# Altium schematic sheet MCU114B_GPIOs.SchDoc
size 431 x 279 mm; Date: Not shown in title block; ApprovedBy: Not shown in title block; CheckedBy: Not shown in title block; Author: Not shown in title block; CompanyName: Not shown in title block; Engineer: Not shown in title block; Organization: Not shown in title block; Address1: Not shown in title block; Address2: Not shown in title block; Address3: Not shown in title block; Address4: Not shown in title block; DocumentNumber: 2; Revision: Use project parameter SCH_Rev; SheetNumber: 2; SheetTotal: 11; PageSetup: Record=PageOptions¦CenterHorizontal=True¦CenterVertical=True¦PrintScale=1.00¦XCorrection=1.00¦YCorrection=1.00¦PrintKind=0¦BorderSize=5000000¦LeftOffset=0¦BottomOffset=0¦Orientation=2¦PaperLength=1000¦PaperWidth=1000¦Scale=100¦PaperSource=15¦PrintQuality=600¦MediaType=1¦DitherType=10¦PaperKind=Letter¦PrintScaleMode=1
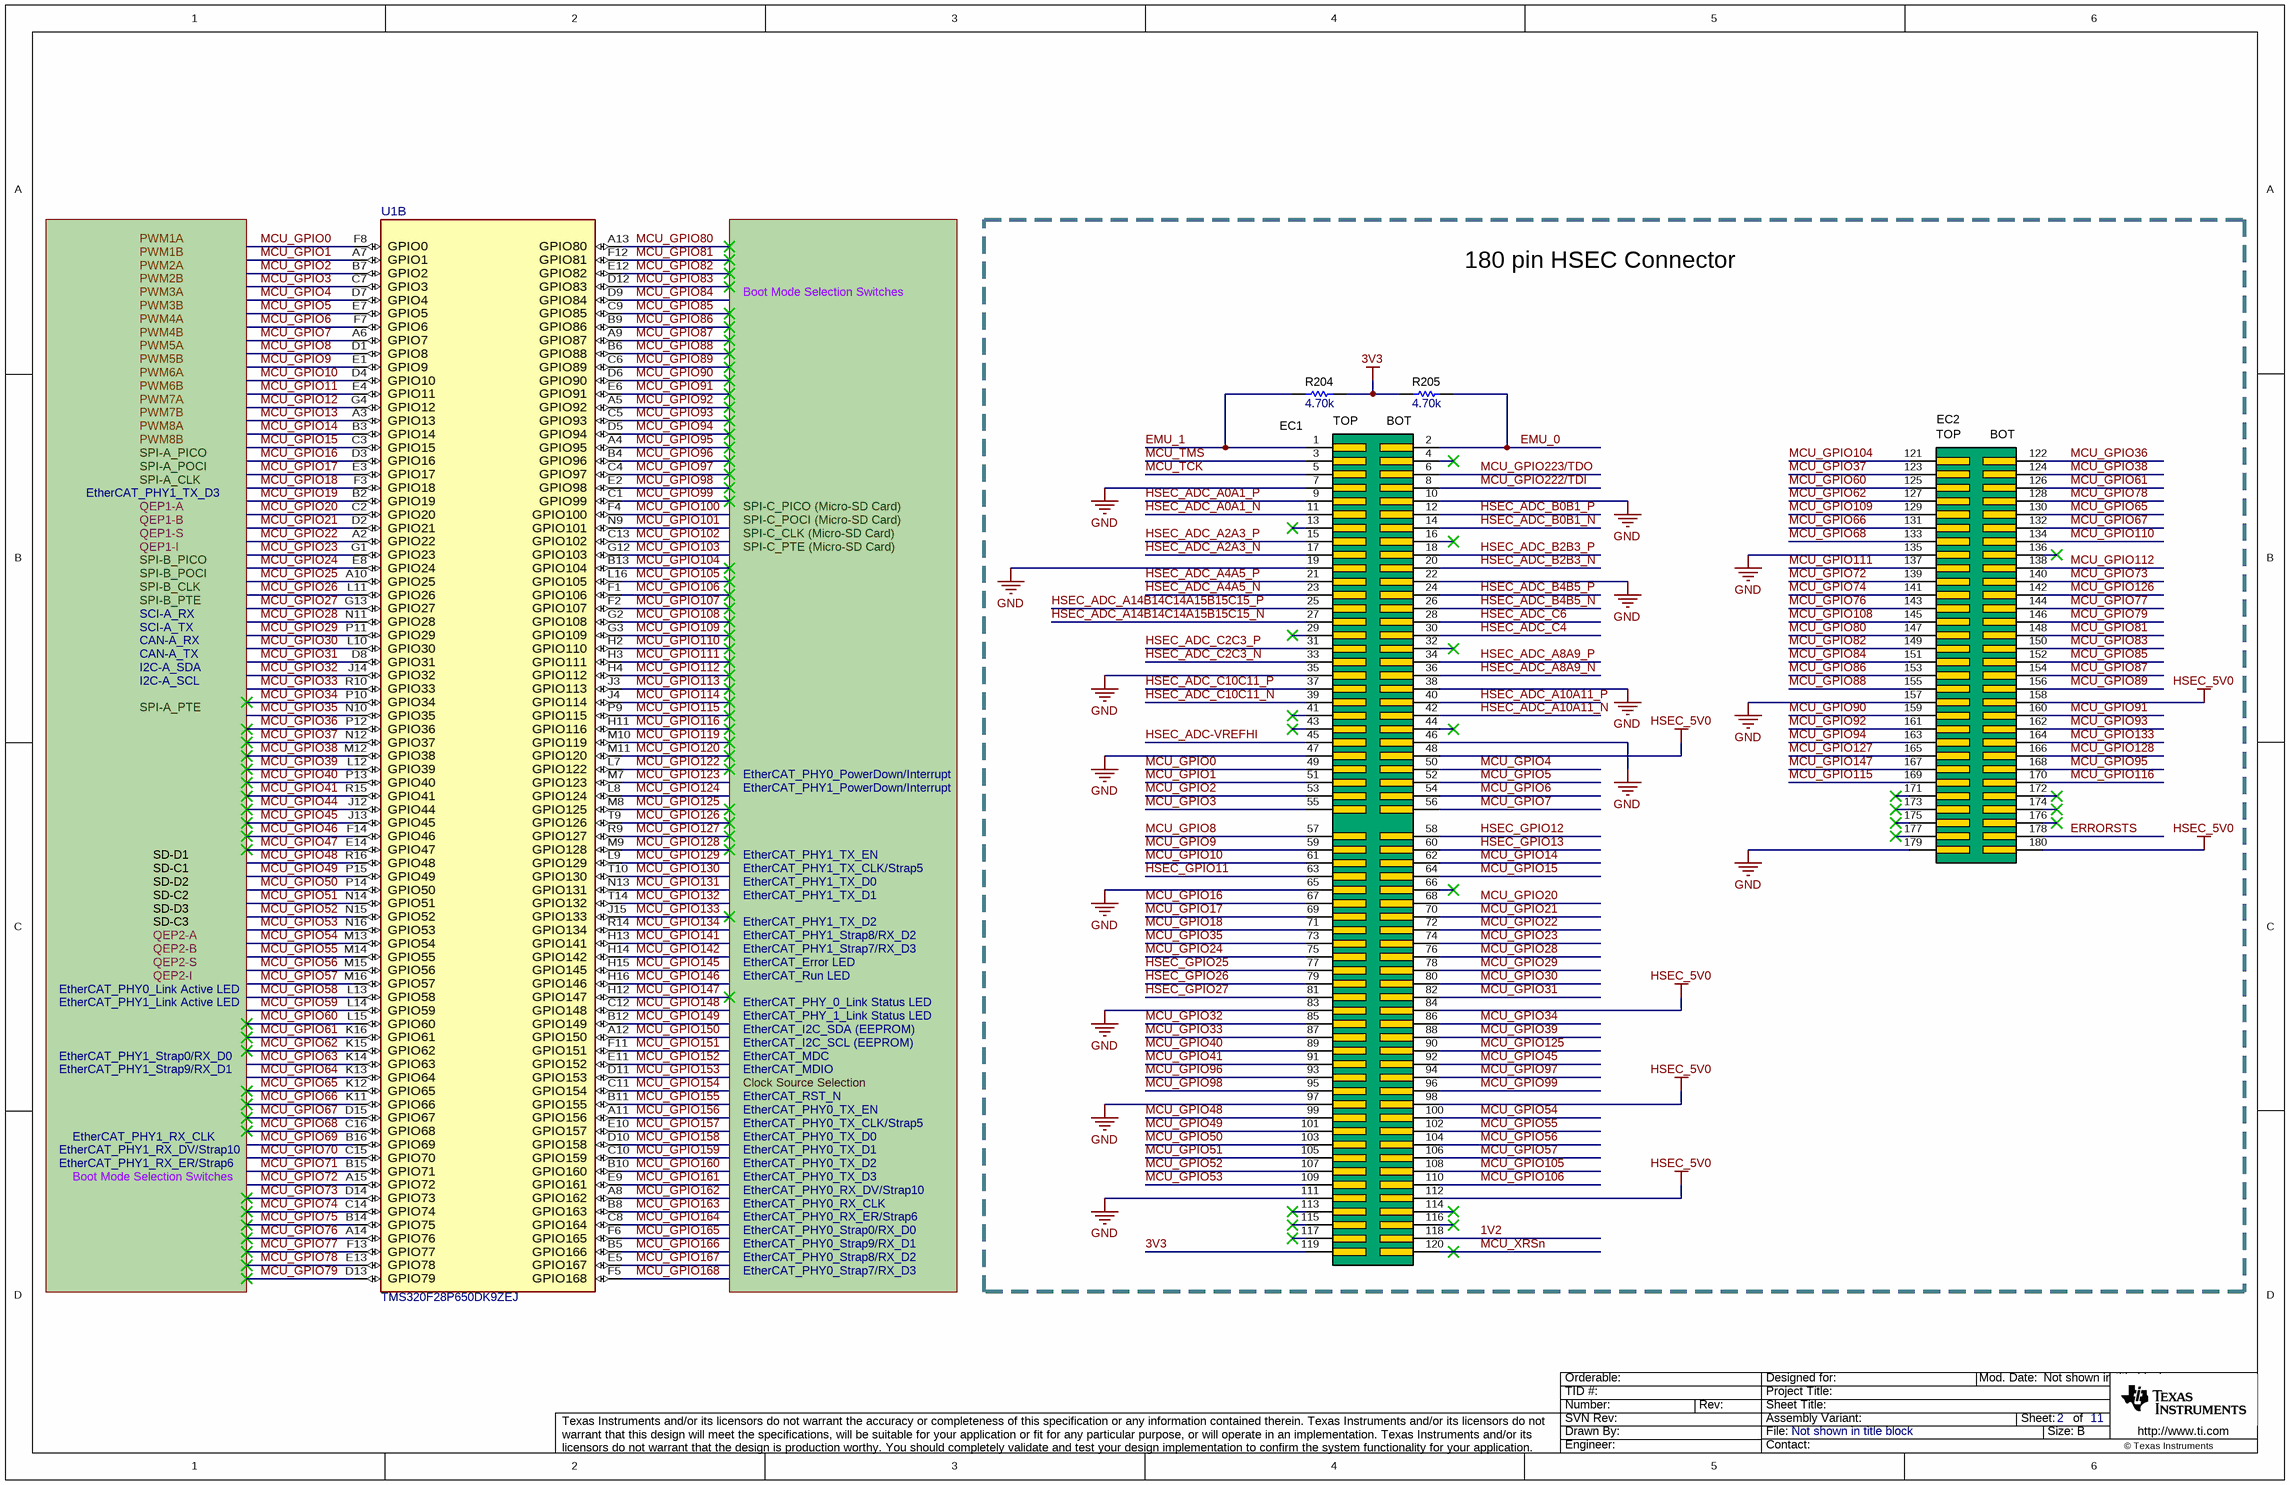
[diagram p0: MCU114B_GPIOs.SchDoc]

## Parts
EC1  controlCARD-120HSEC_Edge  [controlCARD-120HSEC_Edge]  (value not drawn)  (no BOM)
EC2  controlCARD-180HSEC-60pinAddon_Edge  [controlCARD-180HSEC-60pinAddon_Edge]  (value not drawn)  (no BOM)
R204  ValueDisplayed: 4.70k  [0402]  (hidden comment: CRG0402F4K7)
R205  ValueDisplayed: 4.70k  [0402]  (hidden comment: CRG0402F4K7)
U1  TMS320F28P650DK9ZEJ  [ZEJ0256A-MFG]  (part B of 4)

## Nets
3V3: EC1.119 R204.2 R205.1
GND: EC1.7 EC1.10 EC1.19 EC1.22 EC1.35 EC1.38 EC1.46 EC1.47 EC1.65 EC1.83 EC1.97 EC1.111 EC2.135 EC2.157 EC2.179
HSEC_5V0: EC1.48 EC1.84 EC1.98 EC1.112 EC2.158 EC2.180
1V2: EC1.118
EMU_0: EC1.2 R205.2
EMU_1: EC1.1 R204.1
ERRORSTS: EC2.178
HSEC_ADC-VREFHI: EC1.45
HSEC_ADC_A0A1_N: EC1.11
HSEC_ADC_A0A1_P: EC1.9
HSEC_ADC_A2A3_N: EC1.17
HSEC_ADC_A2A3_P: EC1.15
HSEC_ADC_A4A5_N: EC1.23
HSEC_ADC_A4A5_P: EC1.21
HSEC_ADC_A8A9_N: EC1.36
HSEC_ADC_A8A9_P: EC1.34
HSEC_ADC_A10A11_N: EC1.42
HSEC_ADC_A10A11_P: EC1.40
HSEC_ADC_A14B14C14A15B15C15_N: EC1.27
HSEC_ADC_A14B14C14A15B15C15_P: EC1.25
HSEC_ADC_B0B1_N: EC1.14
HSEC_ADC_B0B1_P: EC1.12
HSEC_ADC_B2B3_N: EC1.20
HSEC_ADC_B2B3_P: EC1.18
HSEC_ADC_B4B5_N: EC1.26
HSEC_ADC_B4B5_P: EC1.24
HSEC_ADC_C2C3_N: EC1.33
HSEC_ADC_C2C3_P: EC1.31
HSEC_ADC_C4: EC1.30
HSEC_ADC_C6: EC1.28
HSEC_ADC_C10C11_N: EC1.39
HSEC_ADC_C10C11_P: EC1.37
HSEC_GPIO11: EC1.63
HSEC_GPIO12: EC1.58
HSEC_GPIO13: EC1.60
HSEC_GPIO25: EC1.77
HSEC_GPIO26: EC1.79
HSEC_GPIO27: EC1.81
MCU_GPIO0: EC1.49 U1.F8(GPIO0)
MCU_GPIO1: EC1.51 U1.A7(GPIO1)
MCU_GPIO2: EC1.53 U1.B7(GPIO2)
MCU_GPIO3: EC1.55 U1.C7(GPIO3)
MCU_GPIO4: EC1.50 U1.D7(GPIO4)
MCU_GPIO5: EC1.52 U1.E7(GPIO5)
MCU_GPIO6: EC1.54 U1.F7(GPIO6)
MCU_GPIO7: EC1.56 U1.A6(GPIO7)
MCU_GPIO8: EC1.57 U1.D1(GPIO8)
MCU_GPIO9: EC1.59 U1.E1(GPIO9)
MCU_GPIO10: EC1.61 U1.D4(GPIO10)
MCU_GPIO11: U1.E4(GPIO11)
MCU_GPIO12: U1.G4(GPIO12)
MCU_GPIO13: U1.A3(GPIO13)
MCU_GPIO14: EC1.62 U1.B3(GPIO14)
MCU_GPIO15: EC1.64 U1.C3(GPIO15)
MCU_GPIO16: EC1.67 U1.D3(GPIO16)
MCU_GPIO17: EC1.69 U1.E3(GPIO17)
MCU_GPIO18: EC1.71 U1.F3(GPIO18)
MCU_GPIO19: U1.B2(GPIO19)
MCU_GPIO20: EC1.68 U1.C2(GPIO20)
MCU_GPIO21: EC1.70 U1.D2(GPIO21)
MCU_GPIO22: EC1.72 U1.A2(GPIO22)
MCU_GPIO23: EC1.74 U1.G1(GPIO23)
MCU_GPIO24: EC1.75 U1.E8(GPIO24)
MCU_GPIO25: U1.A10(GPIO25)
MCU_GPIO26: U1.L11(GPIO26)
MCU_GPIO27: U1.G13(GPIO27)
MCU_GPIO28: EC1.76 U1.N11(GPIO28)
MCU_GPIO29: EC1.78 U1.P11(GPIO29)
MCU_GPIO30: EC1.80 U1.L10(GPIO30)
MCU_GPIO31: EC1.82 U1.D8(GPIO31)
MCU_GPIO32: EC1.85 U1.J14(GPIO32)
MCU_GPIO33: EC1.87 U1.R10(GPIO33)
MCU_GPIO34: EC1.86 U1.P10(GPIO34)
MCU_GPIO35: EC1.73 U1.N10(GPIO35)
MCU_GPIO36: EC2.122 U1.P12(GPIO36)
MCU_GPIO37: EC2.123 U1.N12(GPIO37)
MCU_GPIO38: EC2.124 U1.M12(GPIO38)
MCU_GPIO39: EC1.88 U1.L12(GPIO39)
MCU_GPIO40: EC1.89 U1.P13(GPIO40)
MCU_GPIO41: EC1.91 U1.R15(GPIO41)
MCU_GPIO44: U1.J12(GPIO44)
MCU_GPIO45: EC1.92 U1.J13(GPIO45)
MCU_GPIO46: U1.F14(GPIO46)
MCU_GPIO47: U1.E14(GPIO47)
MCU_GPIO48: EC1.99 U1.R16(GPIO48)
MCU_GPIO49: EC1.101 U1.P15(GPIO49)
MCU_GPIO50: EC1.103 U1.P14(GPIO50)
MCU_GPIO51: EC1.105 U1.N14(GPIO51)
MCU_GPIO52: EC1.107 U1.N15(GPIO52)
MCU_GPIO53: EC1.109 U1.N16(GPIO53)
MCU_GPIO54: EC1.100 U1.M13(GPIO54)
MCU_GPIO55: EC1.102 U1.M14(GPIO55)
MCU_GPIO56: EC1.104 U1.M15(GPIO56)
MCU_GPIO57: EC1.106 U1.M16(GPIO57)
MCU_GPIO58: U1.L13(GPIO58)
MCU_GPIO59: U1.L14(GPIO59)
MCU_GPIO60: EC2.125 U1.L15(GPIO60)
MCU_GPIO61: EC2.126 U1.K16(GPIO61)
MCU_GPIO62: EC2.127 U1.K15(GPIO62)
MCU_GPIO63: U1.K14(GPIO63)
MCU_GPIO64: U1.K13(GPIO64)
MCU_GPIO65: EC2.130 U1.K12(GPIO65)
MCU_GPIO66: EC2.131 U1.K11(GPIO66)
MCU_GPIO67: EC2.132 U1.D15(GPIO67)
MCU_GPIO68: EC2.133 U1.C16(GPIO68)
MCU_GPIO69: U1.B16(GPIO69)
MCU_GPIO70: U1.C15(GPIO70)
MCU_GPIO71: U1.B15(GPIO71)
MCU_GPIO72: EC2.139 U1.A15(GPIO72)
MCU_GPIO73: EC2.140 U1.D14(GPIO73)
MCU_GPIO74: EC2.141 U1.C14(GPIO74)
MCU_GPIO75: U1.B14(GPIO75)
MCU_GPIO76: EC2.143 U1.A14(GPIO76)
MCU_GPIO77: EC2.144 U1.F13(GPIO77)
MCU_GPIO78: EC2.128 U1.E13(GPIO78)
MCU_GPIO79: EC2.146 U1.D13(GPIO79)
MCU_GPIO80: EC2.147 U1.A13(GPIO80)
MCU_GPIO81: EC2.148 U1.F12(GPIO81)
MCU_GPIO82: EC2.149 U1.E12(GPIO82)
MCU_GPIO83: EC2.150 U1.D12(GPIO83)
MCU_GPIO84: EC2.151 U1.D9(GPIO84)
MCU_GPIO85: EC2.152 U1.C9(GPIO85)
MCU_GPIO86: EC2.153 U1.B9(GPIO86)
MCU_GPIO87: EC2.154 U1.A9(GPIO87)
MCU_GPIO88: EC2.155 U1.B6(GPIO88)
MCU_GPIO89: EC2.156 U1.C6(GPIO89)
MCU_GPIO90: EC2.159 U1.D6(GPIO90)
MCU_GPIO91: EC2.160 U1.E6(GPIO91)
MCU_GPIO92: EC2.161 U1.A5(GPIO92)
MCU_GPIO93: EC2.162 U1.C5(GPIO93)
MCU_GPIO94: EC2.163 U1.D5(GPIO94)
MCU_GPIO95: EC2.168 U1.A4(GPIO95)
MCU_GPIO96: EC1.93 U1.B4(GPIO96)
MCU_GPIO97: EC1.94 U1.C4(GPIO97)
MCU_GPIO98: EC1.95 U1.E2(GPIO98)
MCU_GPIO99: EC1.96 U1.C1(GPIO99)
MCU_GPIO100: U1.F4(GPIO100)
MCU_GPIO101: U1.N9(GPIO101)
MCU_GPIO102: U1.C13(GPIO102)
MCU_GPIO103: U1.G12(GPIO103)
MCU_GPIO104: EC2.121 U1.B13(GPIO104)
MCU_GPIO105: EC1.108 U1.L16(GPIO105)
MCU_GPIO106: EC1.110 U1.F1(GPIO106)
MCU_GPIO107: U1.F2(GPIO107)
MCU_GPIO108: EC2.145 U1.G2(GPIO108)
MCU_GPIO109: EC2.129 U1.G3(GPIO109)
MCU_GPIO110: EC2.134 U1.H2(GPIO110)
MCU_GPIO111: EC2.137 U1.H3(GPIO111)
MCU_GPIO112: EC2.138 U1.H4(GPIO112)
MCU_GPIO113: U1.J3(GPIO113)
MCU_GPIO114: U1.J4(GPIO114)
MCU_GPIO115: EC2.169 U1.P9(GPIO115)
MCU_GPIO116: EC2.170 U1.H11(GPIO116)
MCU_GPIO119: U1.M10(GPIO119)
MCU_GPIO120: U1.M11(GPIO120)
MCU_GPIO122: U1.L7(GPIO122)
MCU_GPIO123: U1.M7(GPIO123)
MCU_GPIO124: U1.L8(GPIO124)
MCU_GPIO125: EC1.90 U1.M8(GPIO125)
MCU_GPIO126: EC2.142 U1.T9(GPIO126)
MCU_GPIO127: EC2.165 U1.R9(GPIO127)
MCU_GPIO128: EC2.166 U1.M9(GPIO128)
MCU_GPIO129: U1.L9(GPIO129)
MCU_GPIO130: U1.T10(GPIO130)
MCU_GPIO131: U1.N13(GPIO131)
MCU_GPIO132: U1.T14(GPIO132)
MCU_GPIO133: EC2.164 U1.J15(GPIO133)
MCU_GPIO134: U1.R14(GPIO134)
MCU_GPIO141: U1.H13(GPIO141)
MCU_GPIO142: U1.H14(GPIO142)
MCU_GPIO145: U1.H15(GPIO145)
MCU_GPIO146: U1.H16(GPIO146)
MCU_GPIO147: EC2.167 U1.H12(GPIO147)
MCU_GPIO148: U1.C12(GPIO148)
MCU_GPIO149: U1.B12(GPIO149)
MCU_GPIO150: U1.A12(GPIO150)
MCU_GPIO151: U1.F11(GPIO151)
MCU_GPIO152: U1.E11(GPIO152)
MCU_GPIO153: U1.D11(GPIO153)
MCU_GPIO154: U1.C11(GPIO154)
MCU_GPIO155: U1.B11(GPIO155)
MCU_GPIO156: U1.A11(GPIO156)
MCU_GPIO157: U1.E10(GPIO157)
MCU_GPIO158: U1.D10(GPIO158)
MCU_GPIO159: U1.C10(GPIO159)
MCU_GPIO160: U1.B10(GPIO160)
MCU_GPIO161: U1.E9(GPIO161)
MCU_GPIO162: U1.A8(GPIO162)
MCU_GPIO163: U1.B8(GPIO163)
MCU_GPIO164: U1.C8(GPIO164)
MCU_GPIO165: U1.F6(GPIO165)
MCU_GPIO166: U1.B5(GPIO166)
MCU_GPIO167: U1.E5(GPIO167)
MCU_GPIO168: U1.F5(GPIO168)
MCU_GPIO222/TDI: EC1.8
MCU_GPIO223/TDO: EC1.6
MCU_TCK: EC1.5
MCU_TMS: EC1.3
MCU_XRSn: EC1.120

Not connected (* = marked no-connect by the designer): EC1 4* 13* 16* 29* 32* 41* 43* 44* 66* 113* 114* 115* 116* 117*; EC2 136* 171* 172* 173* 174* 175* 176* 177*

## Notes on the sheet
- PWM1A
- PWM1B
- PWM2A
- PWM2B
- PWM3A
- Boot Mode Selection Switches
- 180 pin HSEC Connector
- PWM3B
- PWM4A
- PWM4B
- PWM5A
- PWM5B
- PWM6A
- PWM6B
- PWM7A
- PWM7B
- PWM8A
- EtherCAT_PHY1_TX_D3
- PWM8B
- SPI-A_PICO
- SPI-A_POCI
- SPI-A_CLK
- QEP1-A
- QEP1-B
- QEP1-S
- QEP1-I
- SPI-B_PICO
- SPI-C_PICO (Micro-SD Card)
- SPI-C_POCI (Micro-SD Card)
- SPI-C_CLK (Micro-SD Card)
- SPI-C_PTE (Micro-SD Card)
- SPI-B_POCI
- SPI-B_CLK
- SPI-B_PTE
- SCI-A_RX
- SCI-A_TX
- CAN-A_RX
- CAN-A_TX
- I2C-A_SDA
- I2C-A_SCL
- SPI-A_PTE
- EtherCAT_PHY0_PowerDown/Interrupt
- EtherCAT_PHY1_PowerDown/Interrupt
- SD-D1
- SD-C1
- SD-D2
- SD-C2
- EtherCAT_PHY1_TX_EN
- EtherCAT_PHY1_TX_CLK/Strap5
- EtherCAT_PHY1_TX_D0
- EtherCAT_PHY1_TX_D1
- SD-D3
- SD-C3
- QEP2-A
- QEP2-B
- QEP2-S
- EtherCAT_PHY1_TX_D2
- EtherCAT_PHY1_Strap8/RX_D2
- EtherCAT_PHY1_Strap7/RX_D3
- EtherCAT_Error LED
- EtherCAT_PHY0_Link Active LED
- EtherCAT_PHY1_Link Active LED
- QEP2-I
- EtherCAT_I2C_SDA (EEPROM)
- EtherCAT_Run LED
- EtherCAT_PHY_0_Link Status LED
- EtherCAT_PHY_1_Link Status LED
- EtherCAT_PHY1_Strap0/RX_D0
- EtherCAT_PHY1_Strap9/RX_D1
- EtherCAT_I2C_SCL (EEPROM)
- EtherCAT_MDC
- EtherCAT_MDIO
- Clock Source Selection
- EtherCAT_RST_N
- EtherCAT_PHY1_RX_ER/Strap6
- EtherCAT_PHY1_RX_DV/Strap10
- EtherCAT_PHY1_RX_CLK
- EtherCAT_PHY0_TX_EN
- EtherCAT_PHY0_TX_CLK/Strap5
- EtherCAT_PHY0_TX_D0
- EtherCAT_PHY0_TX_D1
- EtherCAT_PHY0_TX_D2
- EtherCAT_PHY0_TX_D3
- EtherCAT_PHY0_RX_DV/Strap10
- EtherCAT_PHY0_RX_ER/Strap6
- EtherCAT_PHY0_RX_CLK
- EtherCAT_PHY0_Strap0/RX_D0
- EtherCAT_PHY0_Strap9/RX_D1
- EtherCAT_PHY0_Strap8/RX_D2
- EtherCAT_PHY0_Strap7/RX_D3

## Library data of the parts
EC1 = CMP-0003813-3: C2000 controlCARD-120HSEC Edge Connector for Samtec HSEC8-160-01-L-DV-A-BL; Manufacturer: Any; Note: The pin numbering does not match Samtec datasheet
EC2 = CMP-0081961-1: C2000 controlCARD-180HSEC (60-pin addon) Edge connector for Samtec HSEC8-130-01-L-DV-A; Manufacturer: Any; Note: The pin numbering does not match Samtec datasheet
R204 R205 = CMP-0026631-1: RES, 4.70 k, 1%, 0.063 W, 0402; Manufacturer: TE Connectivity; Power_W: 63mW; TempCo: 100 ppm/C; Value_Code: 4k70; U/M: EA; Value: 4.70k; Res_ohm: 4.7k; SizeX_mm: 1; SizeY_mm: 0.5; SizeZ_mm: 0.6; Value2: 0.063W; AEC Qualified: N; AEC Category: Q200
U1 = CMP-0096042-2: Real-Time Microcontroller NFBGA256; Manufacturer: Texas Instruments; AEC Category: Q200; Core Architecture: C28x; Data Bus Width: 32bits; Number Of Ethernet Channels: 1; Number Of Cores: 2; CompType: IC; Number Of I/Os: 159; Interface: I2C,SPI,UART,CAN,USB,LIN,SCI,Ethernet,Other; Number Of Pwm Channels: 36; AEC Qualified: No; Number Of Timers/Counters: 6; Standoff Height: 0.35mm; Number Of Spi Channels: 4; SizeZ_mm: 1.4mm; Number Of Adc Channels: 40; Ram Size: 248KBytes; Frequency_Fixed: 200MHz; Memory Size: 1.28MBytes; Number Of A/D Converters: 3; Memory Type: FLASH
